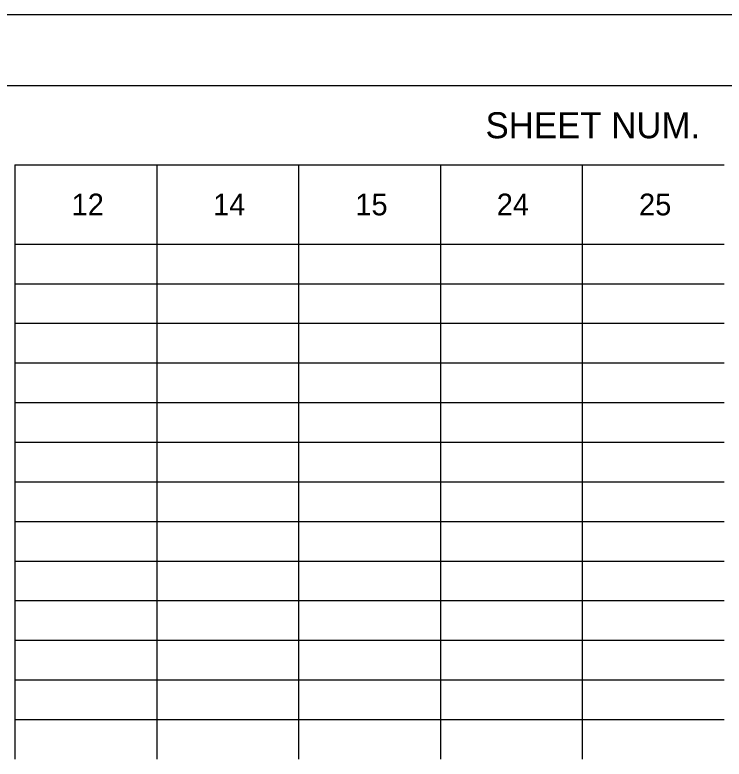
# Model space of a CAD drawing. Extents: x 0 to 34, y 0 to 22.
# Drawn here: x 3.51 to 8.52, y 16.74 to 22 of the extents above; entities that cross this region are included whole.
import ezdxf

# ---------------------------------------------------------------- set-up
doc = ezdxf.new("R2010")
doc.units = 0
for name, color, linetype in [('SH_Border', 7, 'Continuous'), ('SH_Cut_Line', 7, 'Continuous'), ('SH_Text', 7, 'Continuous')]:
    doc.layers.add(name, color=color, linetype=linetype)

msp = doc.modelspace()

# ---------------------------------------------------------------- linework, layer by layer
at = {"layer": 'SH_Border'}
msp.add_lwpolyline([(1.5, 21.5), (33.5, 21.5), (33.5, 0.5), (1.5, 0.5)], close=True, dxfattribs=at)
at = {"layer": 'SH_Cut_Line'}
msp.add_lwpolyline([(0, 0), (34, 0), (34, 22), (0, 22)], close=True, dxfattribs=at)
at = {"layer": 'SH_Text'}
for p, q in [((3.5053, 21.5), (4.508, 21.5)), ((4.508, 21.5), (5.5106, 21.5)), ((5.5106, 21.5), (6.5133, 21.5)), ((6.5133, 21.5), (7.516, 21.5)), ((7.516, 21.5), (8.5186, 21.5)), ((3.5053, 20.94), (4.508, 20.94)), ((3.5053, 20.94), (3.5053, 20.66)), ((4.508, 20.94), (5.5106, 20.94)), ((4.508, 20.94), (4.508, 20.66)), ((5.5106, 20.94), (6.5133, 20.94)), ((5.5106, 20.94), (5.5106, 20.66)), ((6.5133, 20.94), (7.516, 20.94)), ((6.5133, 20.94), (6.5133, 20.66)), ((7.516, 20.94), (8.5186, 20.94)), ((7.516, 20.94), (7.516, 20.66)), ((3.5053, 20.66), (3.5053, 20.38)), ((4.508, 20.66), (4.508, 20.38)), ((5.5106, 20.66), (5.5106, 20.38)), ((6.5133, 20.66), (6.5133, 20.38)), ((7.516, 20.66), (7.516, 20.38)), ((3.5053, 20.38), (4.508, 20.38)), ((3.5053, 20.38), (3.5053, 20.1)), ((4.508, 20.38), (5.5106, 20.38)), ((4.508, 20.38), (4.508, 20.1)), ((5.5106, 20.38), (6.5133, 20.38)), ((5.5106, 20.38), (5.5106, 20.1)), ((6.5133, 20.38), (7.516, 20.38)), ((6.5133, 20.38), (6.5133, 20.1)), ((7.516, 20.38), (8.5186, 20.38)), ((7.516, 20.38), (7.516, 20.1)), ((3.5053, 20.1), (4.508, 20.1)), ((3.5053, 20.1), (3.5053, 18.6999)), ((4.508, 20.1), (5.5106, 20.1)), ((4.508, 20.1), (4.508, 18.6999)), ((5.5106, 20.1), (6.5133, 20.1)), ((5.5106, 20.1), (5.5106, 18.6999)), ((6.5133, 20.1), (7.516, 20.1)), ((6.5133, 20.1), (6.5133, 18.6999)), ((7.516, 20.1), (8.5186, 20.1)), ((7.516, 20.1), (7.516, 18.6999)), ((3.5053, 19.82), (4.508, 19.82)), ((4.508, 19.82), (5.5106, 19.82)), ((5.5106, 19.82), (6.5133, 19.82)), ((6.5133, 19.82), (7.516, 19.82)), ((7.516, 19.82), (8.5186, 19.82)), ((3.5053, 19.5399), (4.508, 19.5399)), ((4.508, 19.5399), (5.5106, 19.5399)), ((5.5106, 19.5399), (6.5133, 19.5399)), ((6.5133, 19.5399), (7.516, 19.5399)), ((7.516, 19.5399), (8.5186, 19.5399)), ((3.5053, 19.2599), (4.508, 19.2599)), ((4.508, 19.2599), (5.5106, 19.2599)), ((5.5106, 19.2599), (6.5133, 19.2599)), ((6.5133, 19.2599), (7.516, 19.2599)), ((7.516, 19.2599), (8.5186, 19.2599)), ((3.5053, 18.9799), (4.508, 18.9799)), ((4.508, 18.9799), (5.5106, 18.9799)), ((5.5106, 18.9799), (6.5133, 18.9799)), ((6.5133, 18.9799), (7.516, 18.9799)), ((7.516, 18.9799), (8.5186, 18.9799)), ((3.5053, 18.6999), (4.508, 18.6999)), ((3.5053, 18.6999), (3.5053, 18.1399)), ((4.508, 18.6999), (5.5106, 18.6999)), ((4.508, 18.6999), (4.508, 18.1399)), ((5.5106, 18.6999), (6.5133, 18.6999)), ((5.5106, 18.6999), (5.5106, 18.1399)), ((6.5133, 18.6999), (7.516, 18.6999)), ((6.5133, 18.6999), (6.5133, 18.1399)), ((7.516, 18.6999), (8.5186, 18.6999)), ((7.516, 18.6999), (7.516, 18.1399)), ((3.5053, 18.4199), (4.508, 18.4199)), ((4.508, 18.4199), (5.5106, 18.4199)), ((5.5106, 18.4199), (6.5133, 18.4199)), ((6.5133, 18.4199), (7.516, 18.4199)), ((7.516, 18.4199), (8.5186, 18.4199)), ((3.5053, 18.1399), (4.508, 18.1399)), ((3.5053, 18.1399), (3.5053, 17.8599)), ((4.508, 18.1399), (5.5106, 18.1399)), ((4.508, 18.1399), (4.508, 17.8599)), ((5.5106, 18.1399), (6.5133, 18.1399)), ((5.5106, 18.1399), (5.5106, 17.8599)), ((6.5133, 18.1399), (7.516, 18.1399)), ((6.5133, 18.1399), (6.5133, 17.8599)), ((7.516, 18.1399), (8.5186, 18.1399)), ((7.516, 18.1399), (7.516, 17.8599)), ((3.5053, 17.8599), (4.508, 17.8599)), ((3.5053, 17.8599), (3.5053, 17.5799)), ((4.508, 17.8599), (5.5106, 17.8599)), ((4.508, 17.8599), (4.508, 17.5799)), ((5.5106, 17.8599), (6.5133, 17.8599)), ((5.5106, 17.8599), (5.5106, 17.5799)), ((6.5133, 17.8599), (7.516, 17.8599)), ((6.5133, 17.8599), (6.5133, 17.5799)), ((7.516, 17.8599), (8.5186, 17.8599)), ((7.516, 17.8599), (7.516, 17.5799)), ((3.5053, 17.5799), (4.508, 17.5799)), ((3.5053, 17.5799), (3.5053, 17.2999)), ((4.508, 17.5799), (5.5106, 17.5799)), ((4.508, 17.5799), (4.508, 17.2999)), ((5.5106, 17.5799), (6.5133, 17.5799)), ((5.5106, 17.5799), (5.5106, 17.2999)), ((6.5133, 17.5799), (7.516, 17.5799)), ((6.5133, 17.5799), (6.5133, 17.2999)), ((7.516, 17.5799), (8.5186, 17.5799)), ((7.516, 17.5799), (7.516, 17.2999)), ((3.5053, 17.2999), (4.508, 17.2999)), ((3.5053, 17.2999), (3.5053, 17.0199)), ((4.508, 17.2999), (5.5106, 17.2999)), ((4.508, 17.2999), (4.508, 17.0199)), ((5.5106, 17.2999), (6.5133, 17.2999)), ((5.5106, 17.2999), (5.5106, 17.0199)), ((6.5133, 17.2999), (7.516, 17.2999)), ((6.5133, 17.2999), (6.5133, 17.0199)), ((7.516, 17.2999), (8.5186, 17.2999)), ((7.516, 17.2999), (7.516, 17.0199)), ((3.5053, 17.0199), (4.508, 17.0199)), ((3.5053, 17.0199), (3.5053, 16.7399)), ((4.508, 17.0199), (5.5106, 17.0199)), ((4.508, 17.0199), (4.508, 16.7399)), ((5.5106, 17.0199), (6.5133, 17.0199)), ((5.5106, 17.0199), (5.5106, 16.7399)), ((6.5133, 17.0199), (7.516, 17.0199)), ((6.5133, 17.0199), (6.5133, 16.7399)), ((7.516, 17.0199), (8.5186, 17.0199)), ((7.516, 17.0199), (7.516, 16.7399))]:
    msp.add_line(p, q, dxfattribs=at)

# ---------------------------------------------------------------- texts
for s, height, p in [('SHEET NUM.', 0.184, (6.832, 21.128)), ('12', 0.15334, (3.9063, 20.5833)), ('14', 0.15334, (4.9061, 20.5833)), ('15', 0.15334, (5.9119, 20.5833)), ('24', 0.15334, (6.9114, 20.5833)), ('25', 0.15334, (7.9172, 20.5833))]:
    msp.add_text(s, height=height, dxfattribs=at).set_placement(p)

doc.saveas('drawing.dxf')
